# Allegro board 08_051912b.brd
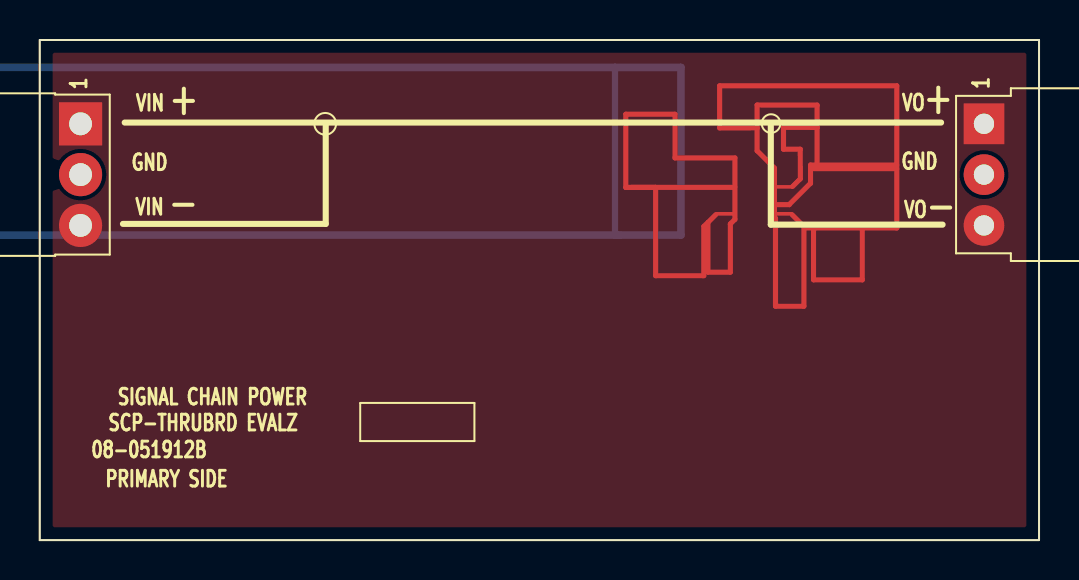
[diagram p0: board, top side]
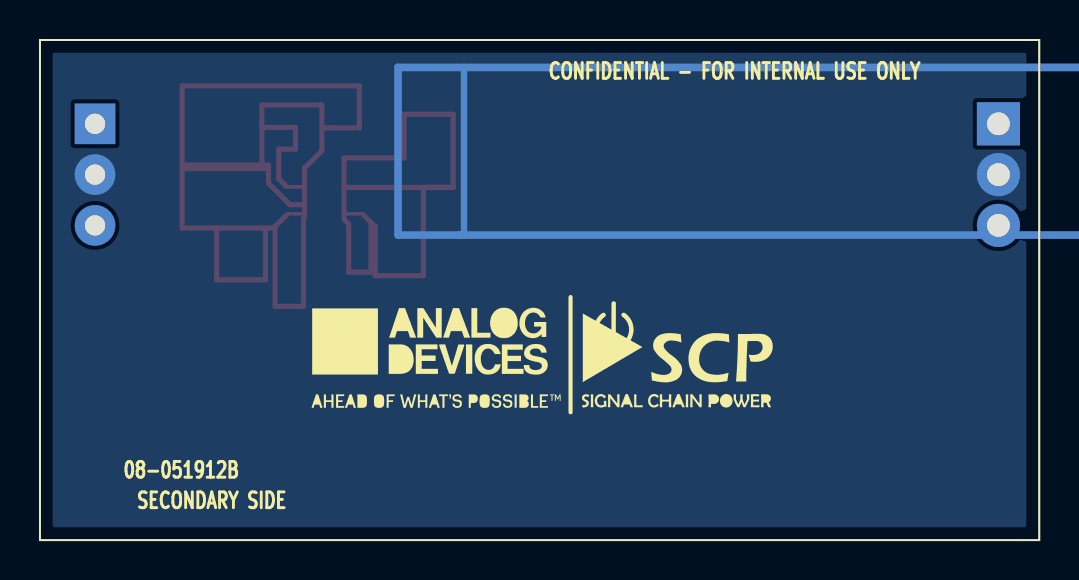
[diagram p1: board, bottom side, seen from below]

Outline 50 x 25 mm; copper layers: TOP, L2_GND, L3_SIG, BOTTOM. Coordinates in mm from the lower left corner of the outline.
Outline path: 0,25 50,25 50,0 0,0 0,25

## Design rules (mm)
constraint set DEFAULT: min track width 0.203

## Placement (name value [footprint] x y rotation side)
INPUT  PBC03SBAN  [CNTHMHDRRA1X3L300W100H145]  2.03 20.81 270 top
NOREF  -  []  0 25 0 top
NOREF#2  -  []  -0.02 25.07 270 top
NOREF#3  -  []  -36.32 105.77 0 top
NOREF#4  -  []  50.02 25.07 180 top
NOREF#5  -  []  50.02 -0.07 90 top
NOREF#6  -  []  50 0 90 top
NOREF#7  -  []  25.1 39.22 0 top
NOREF#8  -  []  -59.69 348.22 0 top
NOREF#9  -  []  0 25 0 top
NOREF#10  -  []  0 0 0 top
NOREF#11  -  []  0 0 0 top
NOREF#12  -  []  -0.02 -0.07 0 top
NOREF#13  -  []  2.03 20.81 0 top
NOREF#14  -  []  -69.98 -54.12 0 top
NOREF#15  -  []  92.2 43.03 0 top
NOREF#16  -  []  2.03 20.81 0 top
NOREF#17  -  []  -19.05 286.11 0 top
NOREF#18  -  []  30.47 9.07 180 bottom
NOREF#19  -  []  18.07 9.28 180 bottom
OUTPUT  PPPC031LGBN-RC  [CNHDRRA1X3H108]  47.24 20.81 270 top

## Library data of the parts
INPUT = CN3P: Tolerance: N/A; User Part Number: UPN; alternate symbols: (CNTHMHDRRA1X3L300W100H145_SCP); part number: CN3P_TH-PBC03SBAN,E034137,CNTHMHDRRA1X3L300W100H145; tolerance: N/A
OUTPUT = CN3P: User Part Number: UPN; Tolerance: N/A; alternate symbols: (CNHDRRA1X3H108_SCP); part number: CN3P_TH-PPPC031LGBN-RC,E034111,CNHDRRA1X3H108; tolerance: N/A

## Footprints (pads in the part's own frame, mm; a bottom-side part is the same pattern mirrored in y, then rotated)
CNHDRRA1X3H108
  rect 2.032x2.032 hole 1.016: 1(0,0)
  round 2.032 hole 1.016: 2(2.54,0) 3(5.08,0)
CNTHMHDRRA1X3L300W100H145
  rect 2.159x2.159 hole 1.143: 1(0,0)
  round 2.159 hole 1.143: 2(2.54,0) 3(5.08,0)

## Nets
AGND: INPUT.2 OUTPUT.2
UNNAMED_2_CN3P_I1_N1: INPUT.1 INPUT.3(N3) OUTPUT.1 OUTPUT.3(N3)

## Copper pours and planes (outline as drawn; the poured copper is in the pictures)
AGND on BOTTOM, L2_GND: 0.64,24.36 49.36,24.36 49.36,0.64 0.64,0.64
UNNAMED_2_CN3P_I1_N1 on TOP, L3_SIG: 0.64,24.36 49.36,24.36 49.36,0.64 0.64,0.64

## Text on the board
Ref Des/Silkscreen Bottom: CONFIDENTIAL - FOR INTERNAL USE ONLY | SECONDARY SIDE | 08-051912B
Ref Des/Silkscreen Top: 08-051912B | GND | VIN | PRIMARY SIDE | SCP-THRUBRD EVALZ | SIGNAL CHAIN POWER | VO | - | +
PAGE_OUTLINE: 18DEC18 | B | AS PER ECR-086427 | 03MAY19 | J.VIERNES | EVALZ
DIMENSION: (REF) | DIA MAX
User.11: VIEW FROM PRIMARY SIDE
User.17: L2 GND | 08-      -07
User.18: L3 SIG | 08-      -08
User.45: FIGURE | SIZE | 40.0 | 45.0 | PLATED | FINISHED HOLES IN MILS | ALL UNITS ARE IN MILS | QTY | 3 | TOLERANCE/NOTES
